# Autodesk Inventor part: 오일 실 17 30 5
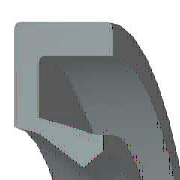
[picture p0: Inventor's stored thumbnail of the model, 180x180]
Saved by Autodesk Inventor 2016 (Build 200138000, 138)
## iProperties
IsCustomPart: 1
Created: 2012-02
Part Number: 오일 실 17 30 5
Material: 고무
Description: 오일 실 - 비스프링, 조립 GA
Document SubType Name: Modeling
Standard: JIS B 2402
Designer: mduedu
Standards Organization: JIS
Language: ko-KR
Size Designation: 17 30 5 A
Categories: <MemberInstance><Categories><Category DisplayName="샤프트 부품" InternalName="7f7aeb1f-a693-4053-b835-cee3144e0d98" Mnemonic="SHFT"><Category DisplayName="실링" Intern
Density: 0.93 g/cm^3
Appearance: Rubber-Black
Author: mduedu
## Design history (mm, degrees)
body "Solid1"
revolve "회전1" stored, may be unused: angle "d27" = 360 deg
fillet "모깎기1" dims "d28" = 0.25 (= 0.05 x b)
sketch "스케치2"
  geometry: L1 (10.636, -3.75)-(11.286, -5); L2 (9.769, -3.438)-(10.636, -3.75); L3 (8.5, -1.375)-(9.769, -3.438); L4 (9.5, -0.75)-(8.5, -1.375); L5 (12.4, -4.375)-(9.5, -0.75); L6 (12.4, -0.25)-(12.4, -4.375); L7 (13.7, -0.25)-(12.4, -0.25); L8 (13.7, 0)-(13.7, -0.25); L9 (15, 0)-(13.7, 0); L10 (15, -5)-(15, 0); L11 (11.286, -5)-(15, -5); L12 (0, -9.6)-(0, 1.6) reference; L13 (28, 0)-(14, 0) reference
  constraints: 22 end point, 3 horizontal, 3 vertical
  dimensions: "d2" = 5 distance of L10.start L9.start (= b); "d4" = 1.3 distance of L9.start L8.start (= 0.1 x dd - 0.1 x Diam); "d6" = 0.25 distance of L8.start L7.start (= 0.05 x b); "d8" = 1 horizontal distance of L4.start L3.start (= 0.0769231 x dd - 0.0769231 x Diam); "d10" = 0.625 vertical distance of L5.start L10.start (= 0.125 x b); "d12" = 1.3 distance of L7.start L6.start (= 0.1 x dd - 0.1 x Diam); "d14" = 0.5 vertical distance of L4.start L6.start (= 0.1 x b); "d16" = 3.71429 distance of L1.end L10.start (= 0.285714 x dd - 0.285714 x Diam); "d18" = 0.65 horizontal distance of L1.start L1.end (= 0.05 x dd - 0.05 x Diam); "d20" = 0.625 vertical distance of L4.start L3.start (= 0.125 x b); "d22" = 1.25 vertical distance of L1.start L1.end (= 0.25 x b); "d24" = 0.86667 horizontal distance of L2.start L1.start (= 0.0666667 x dd - 0.0666667 x Diam); "d26" = 0.3125 vertical distance of L2.start L1.start (= 0.0625 x b); "d29" = 0 distance between parallel lines of L13 L9; "d30" = 8.5 distance from line of L3.start L12 (= 0.5 x Diam); "d31" = 15 distance between parallel lines of L12 L10 (= 0.5 x dd)
other parameters: "Diam" = 17 [user parameter; used in 7 equation terms], "b" = 5 [user parameter; used in 8 equation terms], "d1" = 8 (derived), "d3" = 2 (derived), "d5" = 0.4 (derived), "d7" = 1.53846 (derived), "d9" = 1 (derived), "d11" = 2 (derived), "d13" = 0.8 (derived), "d15" = 5.71429 (derived), "d17" = 1 (derived), "d19" = 1 (derived), "d21" = 2 (derived), "d23" = 1.33333 (derived), "d25" = 0.5 (derived), "d32" = 0
